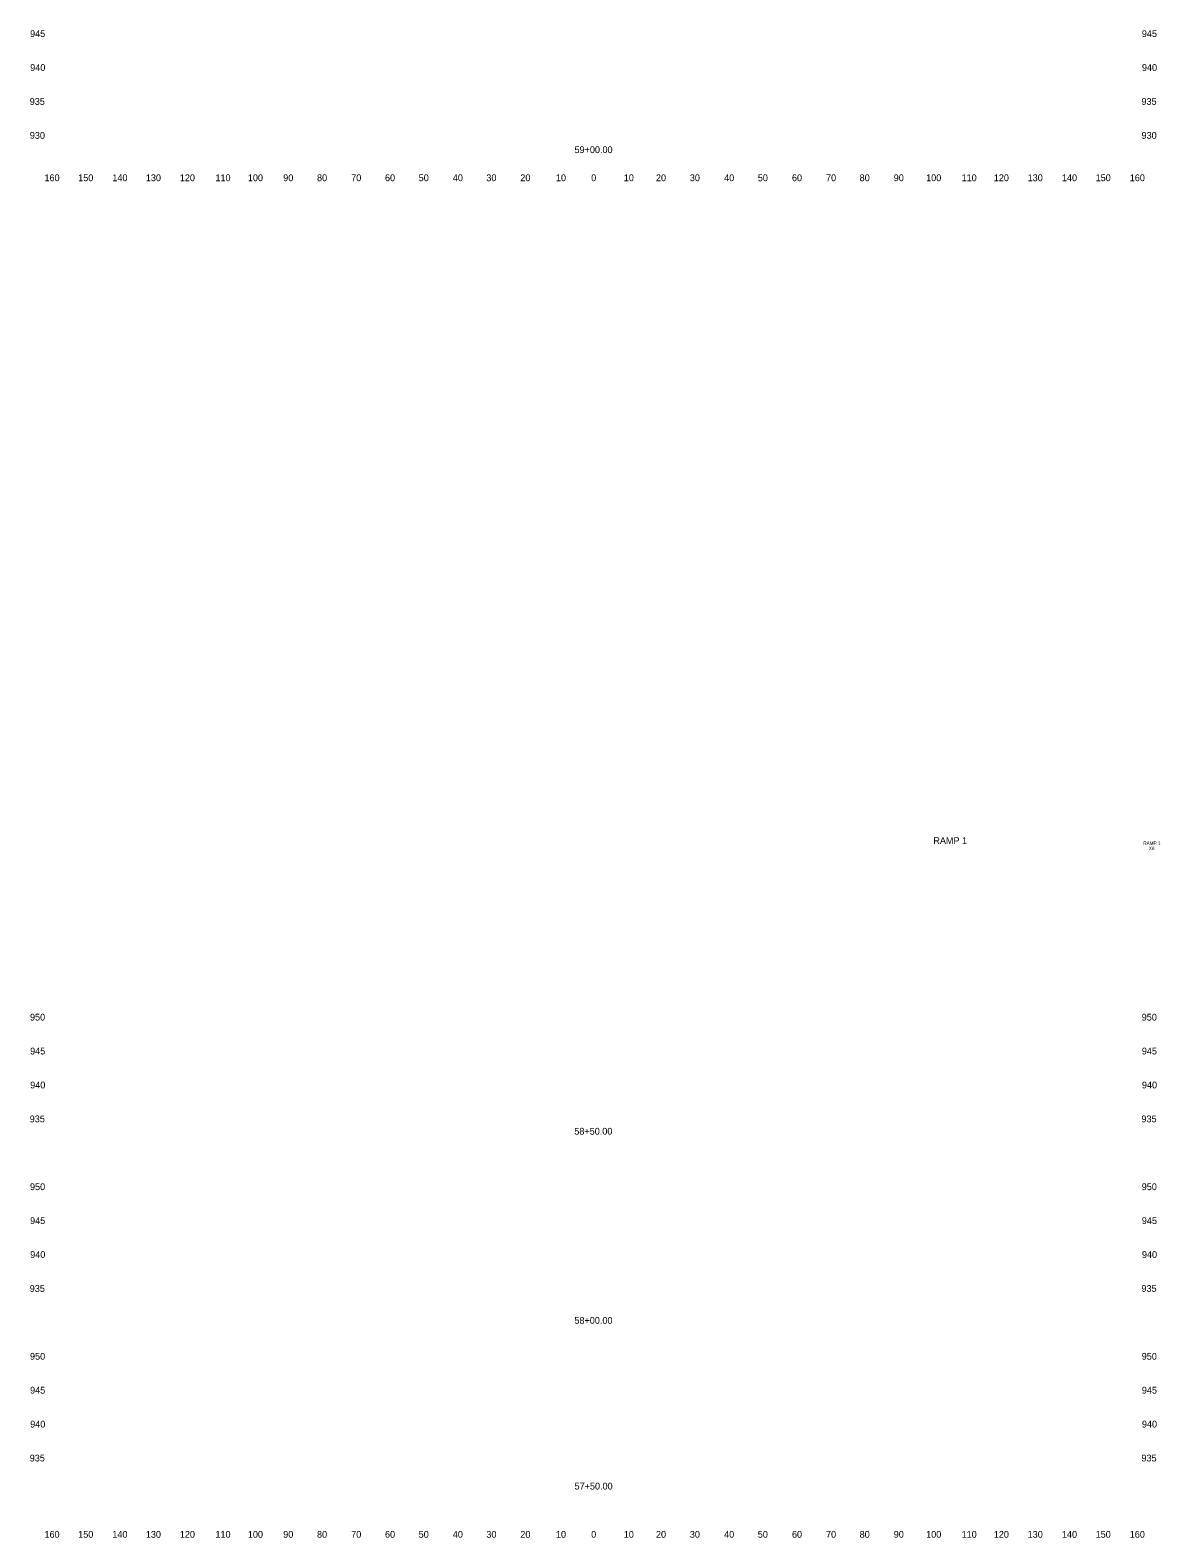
# Model space of a CAD drawing. Extents: x 4994 to 7869, y 4997 to 8804.
# Drawn here: x 4993.9 to 5327, y 6997.5 to 7442 of the extents above; entities that cross this region are included whole.
import ezdxf

# ---------------------------------------------------------------- set-up
doc = ezdxf.new("R2010")
doc.units = 0
for name, color, linetype in [('RD_SHT_ID', 7, 'Continuous'), ('RD_XS_TX_Offset', 7, 'Continuous'), ('RD_XS_TX_Station', 7, 'Continuous')]:
    doc.layers.add(name, color=color, linetype=linetype)

msp = doc.modelspace()

# ---------------------------------------------------------------- texts
at = {"layer": 'RD_SHT_ID'}
for s, height, p in [('RAMP 1', 2, (5260.19, 7202.06)), ('RAMP 1', 1, (5322.06, 7201.8)), ('X6', 1, (5323.71, 7200.3))]:
    msp.add_text(s, height=height, dxfattribs=at).set_placement(p)
at = {"layer": 'RD_XS_TX_Offset'}
for s, p in [('945', (4993.86, 7440)), ('945', (5321.66, 7440)), ('940', (4993.89, 7430)), ('940', (5321.69, 7430)), ('935', (4993.75, 7420)), ('935', (5321.55, 7420)), ('930', (4993.78, 7410)), ('930', (5321.58, 7410)), ('160', (4998.1, 7397.5)), ('150', (5008.04, 7397.5)), ('140', (5018.1, 7397.5)), ('130', (5027.99, 7397.5)), ('120', (5038.01, 7397.5)), ('110', (5048.51, 7397.5)), ('100', (5058.07, 7397.5)), ('90', (5068.5, 7397.5)), ('80', (5078.46, 7397.5)), ('70', (5088.54, 7397.5)), ('60', (5098.5, 7397.5)), ('50', (5108.43, 7397.5)), ('40', (5118.5, 7397.5)), ('30', (5128.39, 7397.5)), ('20', (5138.4, 7397.5)), ('10', (5148.91, 7397.5)), ('0', (5159.3, 7397.5)), ('0', (5159.3, 7397.5)), ('10', (5168.91, 7397.5)), ('20', (5178.4, 7397.5)), ('30', (5188.39, 7397.5)), ('40', (5198.5, 7397.5)), ('50', (5208.43, 7397.5)), ('60', (5218.5, 7397.5)), ('70', (5228.54, 7397.5)), ('80', (5238.46, 7397.5)), ('90', (5248.5, 7397.5)), ('100', (5258.07, 7397.5)), ('110', (5268.51, 7397.5)), ('120', (5278.01, 7397.5)), ('130', (5287.99, 7397.5)), ('140', (5298.1, 7397.5)), ('150', (5308.04, 7397.5)), ('160', (5318.1, 7397.5)), ('950', (4993.83, 7150)), ('950', (5321.63, 7150)), ('945', (4993.86, 7140)), ('945', (5321.66, 7140)), ('940', (4993.89, 7130)), ('940', (5321.69, 7130)), ('935', (4993.75, 7120)), ('935', (5321.55, 7120)), ('950', (4993.83, 7100)), ('950', (5321.63, 7100)), ('945', (4993.86, 7090)), ('945', (5321.66, 7090)), ('940', (4993.89, 7080)), ('940', (5321.69, 7080)), ('935', (4993.75, 7070)), ('935', (5321.55, 7070)), ('950', (4993.83, 7050)), ('950', (5321.63, 7050)), ('945', (4993.86, 7040)), ('945', (5321.66, 7040)), ('940', (4993.89, 7030)), ('940', (5321.69, 7030)), ('935', (4993.75, 7020)), ('935', (5321.55, 7020)), ('160', (4998.1, 6997.5)), ('150', (5008.04, 6997.5)), ('140', (5018.1, 6997.5)), ('130', (5027.99, 6997.5)), ('120', (5038.01, 6997.5)), ('110', (5048.51, 6997.5)), ('100', (5058.07, 6997.5)), ('90', (5068.5, 6997.5)), ('80', (5078.46, 6997.5)), ('70', (5088.54, 6997.5)), ('60', (5098.5, 6997.5)), ('50', (5108.43, 6997.5)), ('40', (5118.5, 6997.5)), ('30', (5128.39, 6997.5)), ('20', (5138.4, 6997.5)), ('10', (5148.91, 6997.5)), ('0', (5159.3, 6997.5)), ('0', (5159.3, 6997.5)), ('10', (5168.91, 6997.5)), ('20', (5178.4, 6997.5)), ('30', (5188.39, 6997.5)), ('40', (5198.5, 6997.5)), ('50', (5208.43, 6997.5)), ('60', (5218.5, 6997.5)), ('70', (5228.54, 6997.5)), ('80', (5238.46, 6997.5)), ('90', (5248.5, 6997.5)), ('100', (5258.07, 6997.5)), ('110', (5268.51, 6997.5)), ('120', (5278.01, 6997.5)), ('130', (5287.99, 6997.5)), ('140', (5298.1, 6997.5)), ('150', (5308.04, 6997.5)), ('160', (5318.1, 6997.5))]:
    msp.add_text(s, height=2, dxfattribs=at).set_placement(p)
at = {"layer": 'RD_XS_TX_Station'}
for s, p in [('59+00.00', (5154.39, 7405.78)), ('58+50.00', (5154.32, 7116.36)), ('58+00.00', (5154.35, 7060.59)), ('57+50.00', (5154.4, 7011.72))]:
    msp.add_text(s, height=2, dxfattribs=at).set_placement(p)

doc.saveas('drawing.dxf')
